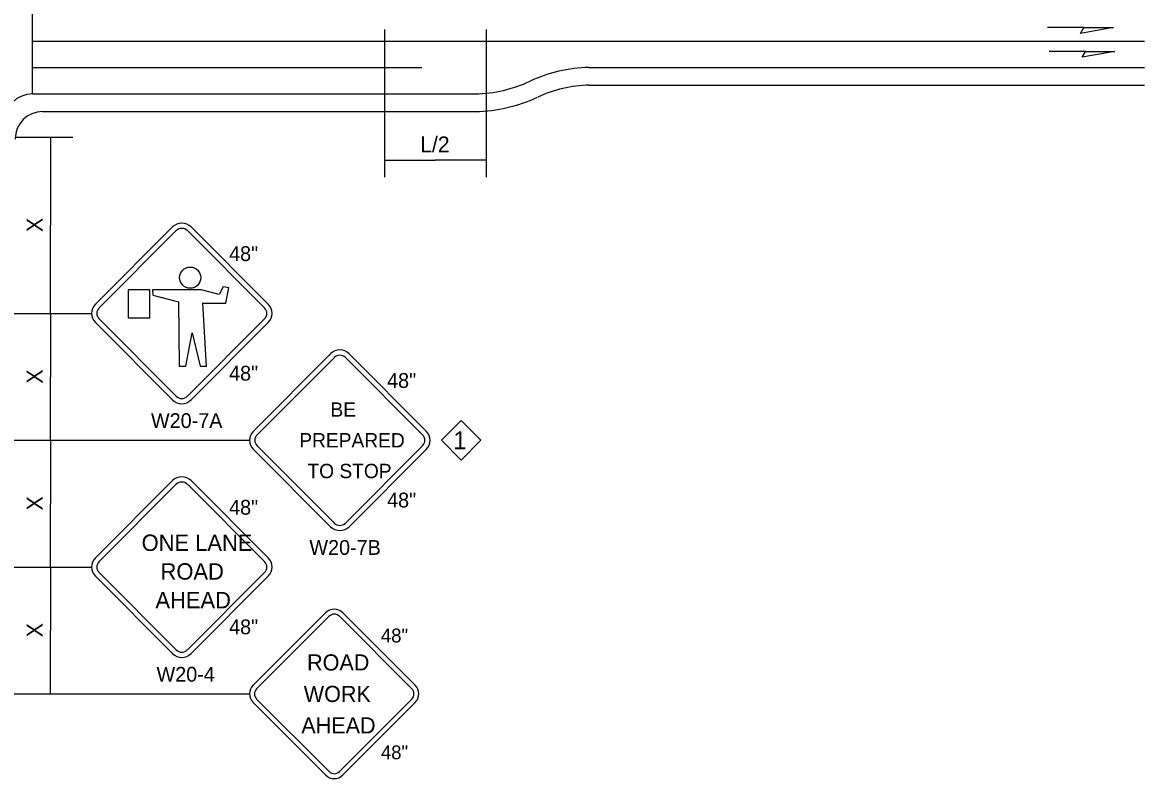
# Model space of a CAD drawing. Extents: x 99988 to 100172, y 99995 to 100047.
# Drawn here: x 100005.501 to 100010.479, y 100002.333 to 100005.686 of the extents above; entities that cross this region are included whole.
import ezdxf

# ---------------------------------------------------------------- set-up
doc = ezdxf.new("R2010")
doc.units = 0
for name, color, linetype in [('Level 15', 7, 'Continuous'), ('Level 20', 7, 'Continuous'), ('SH_DE_DetailBody1Text', 7, 'Continuous'), ('SH_GI_TrafficMvmntArrowRt1Lane', 7, 'Continuous'), ('TR_SN_WarningSigns', 7, 'Continuous'), ('TR_WZ_WorkZoneDetails', 7, 'Continuous')]:
    doc.layers.add(name, color=color, linetype=linetype)

msp = doc.modelspace()

# ---------------------------------------------------------------- linework, layer by layer
at = {"layer": 'Level 15'}
for p, q in [((100005.6247, 100005.1777), (100005.6247, 100004.7867)), ((100007.1073, 100005.0756), (100007.3323, 100005.0756)), ((100007.5573, 100005.0756), (100007.3323, 100005.0756)), ((100005.6247, 100004.3957), (100005.6247, 100004.7867)), ((100005.6247, 100004.3957), (100005.6247, 100004.1145)), ((100005.6247, 100003.8332), (100005.6247, 100004.1145)), ((100005.6247, 100003.8332), (100005.6247, 100003.552)), ((100005.6247, 100003.2707), (100005.6247, 100003.552)), ((100005.6247, 100003.2707), (100005.6247, 100002.9895)), ((100005.6247, 100002.7082), (100005.6247, 100002.9895))]:
    msp.add_line(p, q, dxfattribs=at)
at = {"layer": 'SH_DE_DetailBody1Text'}
msp.add_lwpolyline([(100007.447, 100003.921), (100007.5347, 100003.8332), (100007.447, 100003.7454), (100007.3592, 100003.8332)], close=True, dxfattribs=at)
at = {"layer": 'SH_GI_TrafficMvmntArrowRt1Lane'}
for p, q in [((100010.2099, 100005.6635), (100010.0491, 100005.6635)), ((100010.2165, 100005.5577), (100010.0557, 100005.5577))]:
    msp.add_line(p, q, dxfattribs=at)
for points in [[(100010.3409, 100005.6635), (100010.195, 100005.6378), (100010.2099, 100005.6635)], [(100010.3475, 100005.5577), (100010.2016, 100005.532), (100010.2165, 100005.5577)]]:
    msp.add_lwpolyline(points, close=True, dxfattribs=at)
at = {"layer": 'TR_SN_WarningSigns'}
for p, q in [((100005.8243, 100004.4365), (100006.167, 100004.7792)), ((100005.8406, 100004.4202), (100006.1833, 100004.7629)), ((100006.2322, 100004.7629), (100006.5749, 100004.4202)), ((100006.2486, 100004.7792), (100006.5912, 100004.4365)), ((100006.1833, 100004.0286), (100005.8406, 100004.3712)), ((100006.5749, 100004.3712), (100006.2322, 100004.0286)), ((100006.1669, 100004.0122), (100005.8243, 100004.3549)), ((100006.5912, 100004.3549), (100006.2485, 100004.0122)), ((100006.5254, 100003.874), (100006.8681, 100004.2167)), ((100006.9496, 100004.2167), (100007.2923, 100003.874)), ((100006.5417, 100003.8577), (100006.8844, 100004.2004)), ((100006.9333, 100004.2004), (100007.276, 100003.8577)), ((100006.868, 100003.4497), (100006.5254, 100003.7924)), ((100006.8844, 100003.4661), (100006.5417, 100003.8087)), ((100007.276, 100003.8087), (100006.9333, 100003.4661)), ((100007.2923, 100003.7924), (100006.9496, 100003.4497)), ((100005.8242, 100003.3115), (100006.1669, 100003.6542)), ((100005.8406, 100003.2952), (100006.1833, 100003.6379)), ((100006.2322, 100003.6379), (100006.5749, 100003.2952)), ((100006.2485, 100003.6542), (100006.5912, 100003.3115)), ((100006.1669, 100002.8873), (100005.8242, 100003.2299)), ((100006.1833, 100002.9036), (100005.8406, 100003.2462)), ((100006.5749, 100003.2462), (100006.2322, 100002.9036)), ((100006.5912, 100003.2299), (100006.2485, 100002.8873)), ((100006.5243, 100002.7464), (100006.8456, 100003.0677)), ((100006.9221, 100003.0677), (100007.2433, 100002.7464)), ((100006.5396, 100002.7311), (100006.8609, 100003.0524)), ((100006.9068, 100003.0524), (100007.228, 100002.7311)), ((100006.8456, 100002.3487), (100006.5243, 100002.67)), ((100006.8609, 100002.364), (100006.5396, 100002.6852)), ((100007.228, 100002.6852), (100006.9068, 100002.364)), ((100007.2433, 100002.6699), (100006.9221, 100002.3487))]:
    msp.add_line(p, q, dxfattribs=at)
for points in [[(100006.0778, 100004.5009), (100006.0793, 100004.4769), (100006.1932, 100004.447), (100006.1957, 100004.1625), (100006.2253, 100004.1625), (100006.2535, 100004.309), (100006.289, 100004.1623), (100006.3177, 100004.1623), (100006.3014, 100004.4412), (100006.4025, 100004.4412), (100006.4162, 100004.5089), (100006.3905, 100004.5138), (100006.3741, 100004.4792), (100006.2937, 100004.5009)], [(100005.9691, 100004.5007), (100005.9691, 100004.3759), (100006.0664, 100004.3759), (100006.0664, 100004.5007)]]:
    msp.add_lwpolyline(points, close=True, dxfattribs=at)
msp.add_circle((100006.2448, 100004.5544), 0.0471, dxfattribs=at)
for centre, radius, start, end in [((100006.2077, 100004.7384), 0.0577, 44.9963, 134.9997), ((100006.2077, 100004.7384), 0.0346, 44.9963, 134.9997), ((100005.8651, 100004.3957), 0.0577, 134.9966, 224.9936), ((100005.8651, 100004.3957), 0.0346, 134.9966, 224.9936), ((100006.5504, 100004.3957), 0.0346, 314.9994, 44.9948), ((100006.5504, 100004.3957), 0.0577, 314.9994, 44.9948), ((100006.9088, 100004.1759), 0.0577, 44.9963, 134.9997), ((100006.9088, 100004.1759), 0.0346, 44.9963, 134.9997), ((100006.2077, 100004.053), 0.0346, 225, 314.9996), ((100006.2077, 100004.053), 0.0577, 225, 314.9996), ((100006.5662, 100003.8332), 0.0577, 134.9966, 224.9936), ((100007.2515, 100003.8332), 0.0577, 314.9994, 44.9948), ((100006.5662, 100003.8332), 0.0346, 134.9966, 224.9936), ((100007.2515, 100003.8332), 0.0346, 314.9994, 44.9948), ((100006.2077, 100003.6134), 0.0577, 44.9963, 134.9997), ((100006.2077, 100003.6134), 0.0346, 44.9963, 134.9997), ((100006.9088, 100003.4905), 0.0346, 225, 314.9996), ((100006.9088, 100003.4905), 0.0577, 225, 314.9996), ((100005.8651, 100003.2707), 0.0577, 134.9966, 224.9936), ((100005.8651, 100003.2707), 0.0346, 134.9966, 224.9936), ((100006.5504, 100003.2707), 0.0346, 314.9994, 44.9948), ((100006.5504, 100003.2707), 0.0577, 314.9994, 44.9948), ((100006.8838, 100003.0295), 0.0541, 44.9963, 134.9997), ((100006.8838, 100003.0295), 0.0325, 44.9963, 134.9997), ((100006.2077, 100002.928), 0.0577, 225, 314.9996), ((100006.2077, 100002.928), 0.0346, 225, 314.9996), ((100006.5626, 100002.7082), 0.0541, 134.9966, 224.9936), ((100006.5626, 100002.7082), 0.0325, 134.9966, 224.9936), ((100007.2051, 100002.7082), 0.0325, 314.9994, 44.9948), ((100007.2051, 100002.7082), 0.0541, 314.9994, 44.9948), ((100006.8838, 100002.3869), 0.0541, 225, 314.9996), ((100006.8838, 100002.3869), 0.0325, 225, 314.9996)]:
    msp.add_arc(centre, radius, start, end, dxfattribs=at)
at = {"layer": 'TR_WZ_WorkZoneDetails'}
for p, q in [((100005.5447, 100005.3691), (100005.5447, 100005.9676)), ((100007.1073, 100005.6555), (100007.1073, 100004.9996)), ((100007.5573, 100005.6555), (100007.5573, 100004.9996)), ((100005.5447, 100005.6038), (100010.4791, 100005.6038)), ((100005.5447, 100005.4866), (100007.2729, 100005.4866)), ((100008.0142, 100005.4863), (100010.4791, 100005.4863)), ((100008.0142, 100005.4082), (100010.4791, 100005.4082)), ((100005.5447, 100005.3691), (100007.2729, 100005.3691)), ((100007.2729, 100005.3691), (100007.5096, 100005.3691)), ((100005.5902, 100005.291), (100007.2729, 100005.291)), ((100007.2729, 100005.291), (100007.5105, 100005.291)), ((100007.5573, 100005.2811), (100007.5573, 100005.2697)), ((100005.4722, 100005.1777), (100005.7247, 100005.1777)), ((100005.4439, 100004.3957), (100005.8074, 100004.3957)), ((100005.4439, 100003.8332), (100006.5085, 100003.8332)), ((100005.4439, 100003.2707), (100005.8074, 100003.2707)), ((100005.4439, 100002.7082), (100006.5085, 100002.7082))]:
    msp.add_line(p, q, dxfattribs=at)
for centre, radius, start, end in [((100008.025, 100004.8479), 0.6385, 90.9749, 115.1801), ((100007.4949, 100005.9852), 0.6163, 271.3607, 294.7952), ((100008.025, 100004.8479), 0.5604, 90.9749, 115.1801), ((100005.5447, 100005.247), 0.1221, 90, 180), ((100007.4949, 100005.9852), 0.6944, 271.2818, 294.7952), ((100005.5902, 100005.1689), 0.1221, 90, 180)]:
    msp.add_arc(centre, radius, start, end, dxfattribs=at)

# ---------------------------------------------------------------- texts
at = {"layer": 'Level 20'}
for s, rotation, p in [('L/2', 360, (100007.2656, 100005.1106)), ('X', 90, (100005.5897, 100004.757)), ('X', 90, (100005.5897, 100004.0847)), ('X', 90, (100005.5897, 100003.5222)), ('X', 90, (100005.5897, 100002.9597))]:
    msp.add_text(s, height=0.07, rotation=rotation, dxfattribs=at).set_placement(p)
at = {"layer": 'SH_DE_DetailBody1Text'}
msp.add_text('1', height=0.08, dxfattribs=at).set_placement((100007.4119, 100003.7932))
at = {"layer": 'TR_SN_WarningSigns'}
for s, height, p in [('48"', 0.06563, (100006.4174, 100004.6281)), ('48"', 0.06563, (100006.4174, 100004.0977)), ('48"', 0.06563, (100007.1185, 100004.0656)), ('BE', 0.0636, (100006.8672, 100003.9377)), ('W20-7A', 0.06563, (100006.0709, 100003.8875)), ('PREPARED', 0.0636, (100006.7289, 100003.8014)), ('TO STOP', 0.0636, (100006.7651, 100003.6651)), ('48"', 0.06563, (100006.4174, 100003.5031)), ('48"', 0.06563, (100007.1185, 100003.5352)), ('ONE LANE', 0.07268, (100006.0294, 100003.3423)), ('W20-7B', 0.06563, (100006.7737, 100003.325)), ('ROAD', 0.07268, (100006.1134, 100003.2151)), ('AHEAD', 0.07268, (100006.0907, 100003.0879)), ('48"', 0.06563, (100006.4174, 100002.9727)), ('48"', 0.06152, (100007.0909, 100002.9365)), ('ROAD', 0.07155, (100006.7634, 100002.8121)), ('W20-4', 0.06563, (100006.0956, 100002.7625)), ('WORK', 0.07155, (100006.7487, 100002.6724)), ('AHEAD', 0.07155, (100006.7379, 100002.5328)), ('48"', 0.06152, (100007.0909, 100002.4183))]:
    msp.add_text(s, height=height, dxfattribs=at).set_placement(p)

doc.saveas('drawing.dxf')
